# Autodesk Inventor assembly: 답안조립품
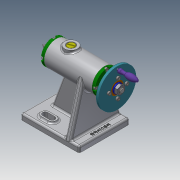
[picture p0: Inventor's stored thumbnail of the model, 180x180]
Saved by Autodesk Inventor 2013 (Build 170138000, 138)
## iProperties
Created: 2019-10
Part Number: 답안조립품
Document SubType Name: Assembly
Designer: a
Author: a
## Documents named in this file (18)
- C:\Users\a\Desktop\491004V1020\답안조립품.iam
- C:\Users\a\Desktop\491004V1020\본체.ipt
- C:\Users\a\Desktop\491004V1020\나사.ipt
- C:\Users\a\Desktop\491004V1020\나사축.ipt
- C:\Users\a\Desktop\491004V1020\너트 M8.ipt
- C:\Users\a\Desktop\491004V1020\돌림판.ipt
- C:\Users\a\Desktop\491004V1020\멈춤나사 M3.ipt
- C:\Users\a\Desktop\491004V1020\볼트 M3.ipt
- C:\Users\a\Desktop\491004V1020\부시.ipt
- C:\Users\a\Desktop\491004V1020\센터.ipt
- C:\Users\a\Desktop\491004V1020\센터홀더.ipt
- C:\Users\a\Desktop\491004V1020\슬리브.ipt
- C:\Users\a\Desktop\491004V1020\와셔.ipt
- C:\Users\a\Desktop\491004V1020\중공축.ipt
- C:\Users\a\Desktop\491004V1020\커버.ipt
- C:\Users\a\Desktop\491004V1020\키 4 x 4 x 10.ipt
- C:\Users\a\Desktop\491004V1020\플랜지.ipt
- C:\Users\a\Desktop\491004V1020\핸들.ipt
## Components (2 placed, 2 different names)
1. 플랜지:1
2. 핸들:1 — 플러쉬:1
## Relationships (1: Flush 1)
- 플러쉬:1 [Flush]: 핸들:1
